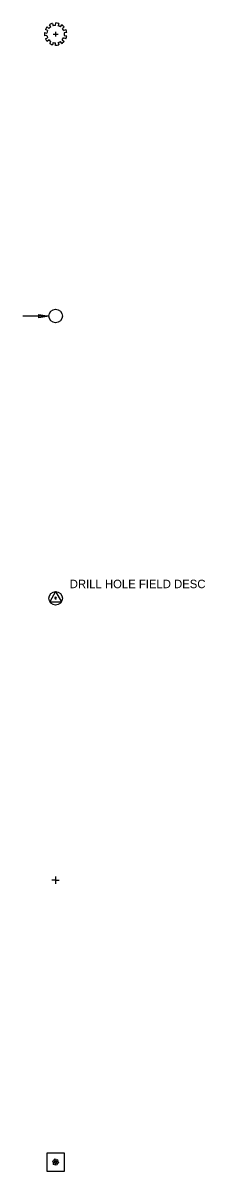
# Model space of a CAD drawing. Extents: x 98 to 2902, y -6 to 903.
# Drawn here: x 494.2 to 526.5, y 698.4 to 902 of the extents above; entities that cross this region are included whole.
import ezdxf

# ---------------------------------------------------------------- set-up
doc = ezdxf.new("R2010")
doc.units = 0
for name, color, linetype in [('V-CHAN-SYMB', 7, 'Continuous'), ('V-SITE-VEGE', 7, 'Continuous'), ('V-SSWR-DEVC', 7, 'Continuous'), ('V-STRM-DEVC', 7, 'Continuous'), ('V-SURV-DATA', 7, 'Continuous')]:
    doc.layers.add(name, color=color, linetype=linetype)

msp = doc.modelspace()

# ---------------------------------------------------------------- linework, layer by layer
at = {"layer": 'V-CHAN-SYMB'}
msp.add_lwpolyline([(501.59, 698.41), (501.59, 701.59), (498.41, 701.59), (498.41, 698.41)], close=True, dxfattribs=at)
for centre in [(499.66, 700.08), (499.89, 700.36), (500.23, 700.29), (499.77, 699.72), (500, 700), (500.11, 699.65), (500.34, 699.94)]:
    msp.add_ellipse(centre, major_axis=(0, 0.187), ratio=0.925822, dxfattribs=at)
at = {"layer": 'V-SITE-VEGE'}
for p, q in [((499.46, 901.89), (499.56, 901.47)), ((500, 901.53), (500.01, 901.96)), ((500.57, 901.88), (500.45, 901.47)), ((498.03, 900.25), (498.46, 900.18)), ((498.46, 899.76), (498.04, 899.69)), ((498.58, 900.61), (498.19, 900.78)), ((498.49, 901.26), (498.81, 900.98)), ((499.17, 901.3), (498.93, 901.65)), ((499.58, 900), (500.42, 900)), ((500, 900.42), (500, 899.58)), ((500.84, 901.29), (501.08, 901.64)), ((501.51, 901.27), (501.19, 900.99)), ((501.42, 900.62), (501.8, 900.82)), ((501.97, 900.25), (501.54, 900.19)), ((501.54, 899.75), (501.97, 899.7)), ((498.19, 899.16), (498.58, 899.35)), ((498.83, 898.96), (498.5, 898.68)), ((498.94, 898.3), (499.15, 898.68)), ((499.58, 898.48), (499.46, 898.07)), ((500, 897.99), (500, 898.42)), ((500.43, 898.49), (500.56, 898.08)), ((501.08, 898.31), (500.85, 898.68)), ((501.17, 898.95), (501.5, 898.68)), ((501.81, 899.15), (501.41, 899.31))]:
    msp.add_line(p, q, dxfattribs=at)
for radius, start, end in [(1.98, 105.972, 122.5562), (1.98, 73.2952, 89.5718), (1.98, 172.27, 188.583), (1.98, 139.7777, 156.0738), (1.56, 156.0557, 172.7558), (1.56, 188.0619, 204.0332), (1.56, 122.254, 140.086), (1.56, 89.9461, 106.3473), (1.56, 57.451, 73.0843), (1.98, 40.7122, 57.1166), (1.56, 24.4529, 40.4774), (1.56, 351.5431, 7.6203), (1.98, 7.9671, 24.8625), (1.98, 204.5394, 220.9852), (1.56, 221.2062, 236.7795), (1.98, 237.6108, 254.1981), (1.56, 254.31, 270.043), (1.98, 270.0356, 286.342), (1.56, 285.9559, 303.0564), (1.98, 302.8434, 319.0222), (1.56, 318.6432, 334.5795), (1.98, 335.3123, 351.7042)]:
    msp.add_arc((500, 899.98), radius, start, end, dxfattribs=at)
at = {"layer": 'V-SSWR-DEVC'}
msp.add_line((498.81, 850), (494.2, 850), dxfattribs=at)
msp.add_lwpolyline([(497.02, 850.3), (498.81, 850), (497.02, 849.7)], close=True, dxfattribs=at)
msp.add_circle((500, 850), 1.19, dxfattribs=at)
at = {"layer": 'V-STRM-DEVC'}
for p, q in [((500, 750), (499.35, 750)), ((500, 750.65), (500, 749.35)), ((500, 750), (500.65, 750))]:
    msp.add_line(p, q, dxfattribs=at)
at = {"layer": 'V-SURV-DATA'}
for p, q in [((500, 801.14), (498.97, 799.35)), ((500, 801.14), (501.03, 799.35)), ((498.97, 799.35), (501.03, 799.35))]:
    msp.add_line(p, q, dxfattribs=at)
msp.add_circle((500, 799.95), 1.19, dxfattribs=at)
msp.add_arc((500, 800), 0.165, 92.2877, 90.5674, dxfattribs=at)

# ---------------------------------------------------------------- texts
msp.add_text('DRILL HOLE FIELD DESC', height=1.5, dxfattribs=at).set_placement((502.5, 801.75))

doc.saveas('drawing.dxf')
